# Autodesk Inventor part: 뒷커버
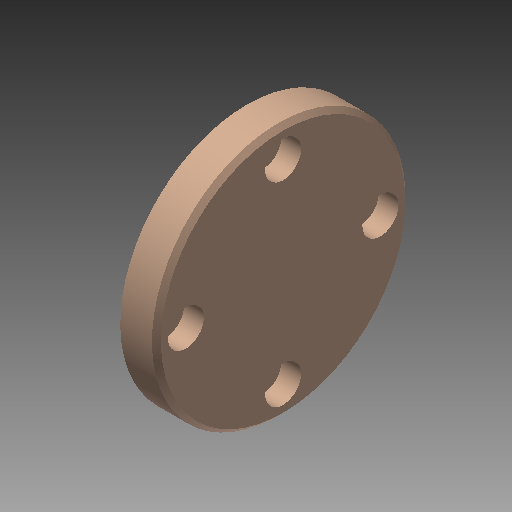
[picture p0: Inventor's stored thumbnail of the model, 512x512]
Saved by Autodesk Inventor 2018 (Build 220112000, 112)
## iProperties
Created: 2024-01
Part Number: 뒷커버
Material: 알루미늄 6061
Document SubType Name: Modeling
Designer: mdu-01
Density: 1 g/cm^3
Appearance: 기본값(1)
Author: mdu-01
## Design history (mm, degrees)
sketch "스케치1"
  geometry: L1 (0, 0)-(-9, 0); L2 (-9, 0)-(-9, 14.5); L3 (-9, 14.5)-(-12, 14.5); L4 (-12, 14.5)-(-12, 16.5); L5 (-11, 17.5)-(-8, 17.5); L6 (-8, 17.5)-(-8, 28); L7 (-8, 28)-(-1, 28); L8 (0, 27)-(0, 0); L9 (-12, 16.5)-(-11, 17.5); L10 (-1, 28)-(0, 27); 2 further points
  constraints: 20 end point, 6 parallel, 4 point on line, 1 horizontal, 1 perpendicular
  dimensions: "d0" = 56 diameter of L7 L1; "d2" = 8 distance between parallel lines of L8 L6; "d3" = 3 distance between parallel lines of L2 L4; "d4" = 4 distance between parallel lines of L6 L4; "d5" = 29 diameter of L3 L1; "d6" = 35 diameter of L5 L1; "d7" = 1 distance of L4.end point (-12, 17.5); "d8" = 1 distance of L5.start point (-12, 17.5) (= d7); "d9" = 1 distance of L7.end point (0, 28) (= d7); "d10" = 1 distance of L8.start point (0, 28) (= d9)
revolve "회전1" sketch "스케치1" stored, may be unused: angle "d11" = 90 deg
sketch "스케치2" dims "d12" = 43
  geometry: 3 further points
  constraints: 2 vertical alignment, 1 coincident, 2 other
hole "구멍1" sketch "스케치2" at (0, 21.5) diameter "d13" = 4.5; stored, may be unused: countersink angle "d17" = 90 deg, drill point angle "d19" = 118 deg; dims "d14" = 6, "d15" = 8, "d16" = 4.4, "d18" = 8
node "솔리드1"
pattern_circular "원형 패턴1" dims angle "d21" = 360 deg
